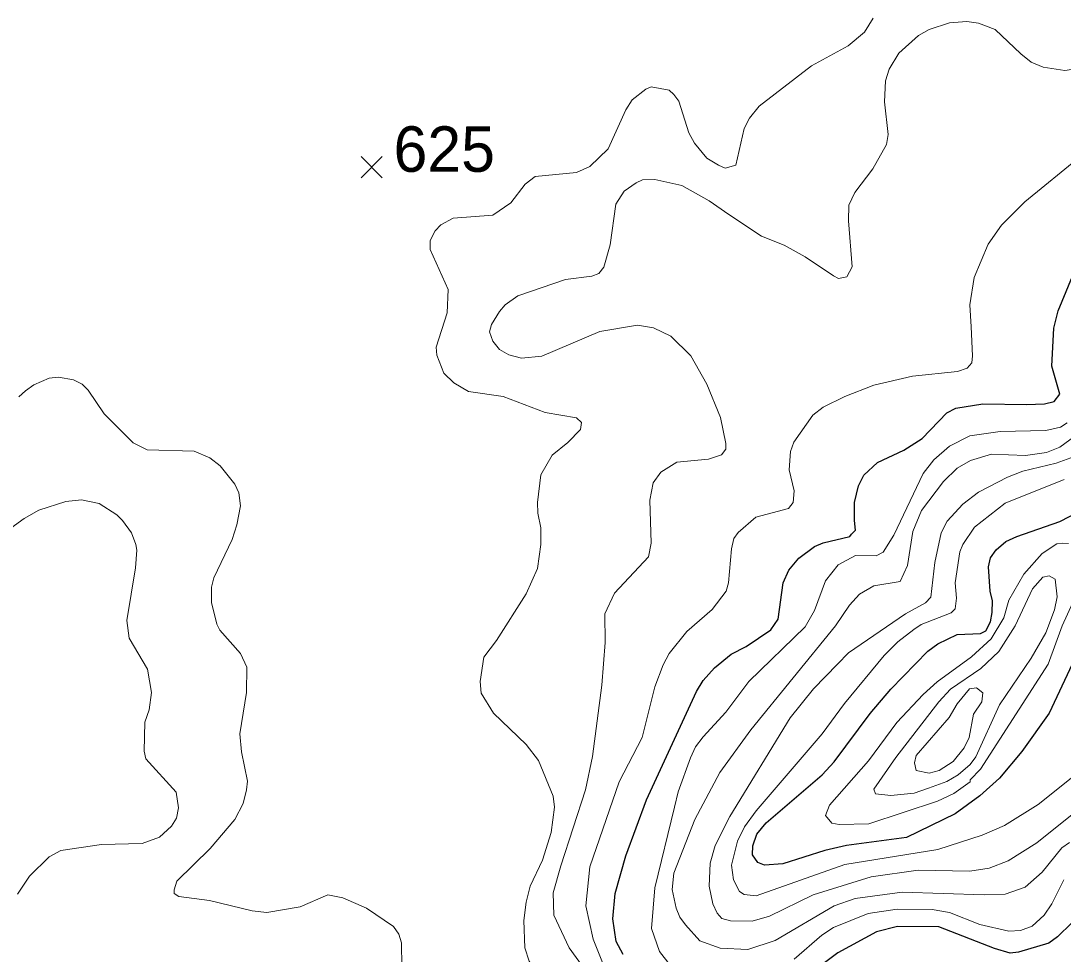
# Model space of a CAD drawing. Extents: x 294.2 to 320.3, y 7482.7 to 7510.7.
# Drawn here: x 308.568 to 310.402, y 7489.428 to 7491.07 of the extents above; entities that cross this region are included whole.
import ezdxf
from ezdxf.enums import TextEntityAlignment as Align

# ---------------------------------------------------------------- set-up
doc = ezdxf.new("R2010")
doc.units = 0
doc.header["$LTSCALE"] = 0.032
for name, color, linetype, lineweight in [('1', 7, 'Continuous', 25), ('2', 7, 'Continuous', 13), ('21', 7, 'Continuous', 25)]:
    doc.layers.add(name, color=color, linetype=linetype, lineweight=lineweight)
doc.layers.add('61', color=7, linetype='Continuous')

msp = doc.modelspace()

# ---------------------------------------------------------------- linework, layer by layer
at = {"layer": '1'}
for points in [[(309.6282, 7489.427), (309.6154, 7489.45), (309.6097, 7489.4896), (309.6141, 7489.5343), (309.6327, 7489.6007), (309.669, 7489.699), (309.7572, 7489.8896), (309.769, 7489.9093), (309.7889, 7489.9313), (309.818, 7489.9557), (309.8447, 7489.969), (309.888, 7489.9981), (309.9008, 7490.017), (309.9098, 7490.0808), (309.9193, 7490.1031), (309.9372, 7490.1242), (309.9647, 7490.1446), (309.98, 7490.1516), (310.0266, 7490.1625), (310.0298, 7490.1664), (310.0366, 7490.1739), (310.0349, 7490.1906), (310.0349, 7490.2225), (310.0419, 7490.2519), (310.0515, 7490.2704), (310.0758, 7490.2928), (310.1218, 7490.3145), (310.1543, 7490.3349), (310.1977, 7490.3802), (310.2137, 7490.3885), (310.261, 7490.3962), (310.3376, 7490.3949), (310.3695, 7490.3962), (310.3867, 7490.4), (310.3963, 7490.4128), (310.3823, 7490.462), (310.3861, 7490.529), (310.3937, 7490.5597), (310.4257, 7490.6376)], [(310.418, 7489.9378), (310.3778, 7489.8516), (310.3299, 7489.7839), (310.2903, 7489.7373), (310.2558, 7489.706), (310.2124, 7489.6747), (310.1269, 7489.6326), (310.0209, 7489.6185), (309.9829, 7489.6098), (309.9091, 7489.5867), (309.8764, 7489.584), (309.8647, 7489.5888), (309.8558, 7489.6023), (309.8564, 7489.6184), (309.8631, 7489.6388), (309.8797, 7489.6587), (309.9779, 7489.7432), (309.9995, 7489.7658), (310.0627, 7489.8508), (310.0992, 7489.8939), (310.1641, 7489.9606), (310.1819, 7489.9735), (310.2157, 7489.9902), (310.2568, 7489.9918), (310.2662, 7489.9967), (310.2745, 7490.0123), (310.2773, 7490.029), (310.2779, 7490.0494), (310.274, 7490.0661), (310.2712, 7490.1089), (310.2746, 7490.125), (310.2845, 7490.139), (310.3012, 7490.1535), (310.3206, 7490.1626), (310.3963, 7490.1887), (310.4295, 7490.2059)], [(310.4174, 7489.4826), (310.3925, 7489.4582), (310.3771, 7489.4467), (310.324, 7489.431), (310.3091, 7489.4294), (310.2816, 7489.4373), (310.1837, 7489.4757), (310.1106, 7489.4765), (310.0739, 7489.4671), (310.0055, 7489.4301), (309.898, 7489.3492)]]:
    msp.add_lwpolyline(points, dxfattribs=at)
at = {"layer": '2'}
for points in [[(309.4551, 7489.4385), (309.4533, 7489.487), (309.4571, 7489.5189), (309.4641, 7489.547), (309.4858, 7489.593), (309.5011, 7489.6415), (309.5069, 7489.6862), (309.5049, 7489.7054), (309.4788, 7489.7686), (309.4571, 7489.7967), (309.3996, 7489.8516), (309.3779, 7489.8867), (309.376, 7489.9071), (309.3824, 7489.9499), (309.4047, 7489.9792), (309.4571, 7490.0616), (309.4769, 7490.1063), (309.4832, 7490.1485), (309.4832, 7490.1778), (309.4775, 7490.2034), (309.4769, 7490.2225), (309.4832, 7490.2711), (309.5031, 7490.3055), (309.5305, 7490.3279), (309.5529, 7490.3508), (309.5547, 7490.363), (309.5459, 7490.3713), (309.4909, 7490.3808), (309.4169, 7490.4089), (309.3556, 7490.4179), (309.33, 7490.4326), (309.3121, 7490.4498), (309.3, 7490.4818), (309.2988, 7490.4958), (309.3179, 7490.5558), (309.3198, 7490.5973), (309.2885, 7490.6675), (309.2885, 7490.6835), (309.2968, 7490.7001), (309.307, 7490.711), (309.3288, 7490.7225), (309.3983, 7490.7276), (309.4303, 7490.7493), (309.4552, 7490.7825), (309.473, 7490.7958), (309.5459, 7490.8029), (309.5695, 7490.8137), (309.6014, 7490.8444), (309.6327, 7490.9134), (309.6435, 7490.9306), (309.6678, 7490.9497), (309.6774, 7490.9536), (309.7087, 7490.9478), (309.7169, 7490.9402), (309.7259, 7490.9287), (309.7437, 7490.8725), (309.7534, 7490.8546), (309.775, 7490.8284), (309.7955, 7490.8157), (309.8076, 7490.8106), (309.8261, 7490.8157), (309.8408, 7490.8802), (309.8504, 7490.8987), (309.867, 7490.9197), (309.9596, 7490.9906), (310.024, 7491.0257), (310.0528, 7491.05), (310.0681, 7491.0743)], [(309.5746, 7489.381), (309.5331, 7489.4385), (309.5056, 7489.496), (309.5049, 7489.5355), (309.5184, 7489.5828), (309.5618, 7489.7169), (309.5739, 7489.7756), (309.5905, 7489.9007), (309.5963, 7489.9761), (309.5956, 7490.0265), (309.6129, 7490.0629), (309.6723, 7490.1267), (309.6773, 7490.151), (309.6748, 7490.2264), (309.6806, 7490.257), (309.694, 7490.2755), (309.7221, 7490.2934), (309.7783, 7490.2985), (309.8012, 7490.3062), (309.8089, 7490.3164), (309.8089, 7490.326), (309.7993, 7490.3719), (309.7751, 7490.4307), (309.747, 7490.4805), (309.7118, 7490.5149), (309.6812, 7490.5296), (309.6531, 7490.5341), (309.5867, 7490.5233), (309.4846, 7490.4798), (309.4488, 7490.476), (309.4264, 7490.4824), (309.4105, 7490.4913), (309.3983, 7490.506), (309.3926, 7490.5226), (309.3964, 7490.5354), (309.4105, 7490.5584), (309.42, 7490.5699), (309.4424, 7490.5858), (309.5267, 7490.6145), (309.5727, 7490.6203), (309.5848, 7490.6254), (309.5937, 7490.6362), (309.6052, 7490.6759), (309.6148, 7490.7474), (309.6295, 7490.7704), (309.6506, 7490.785), (309.662, 7490.7901), (309.6838, 7490.7908), (309.731, 7490.7799), (309.7795, 7490.7531), (309.814, 7490.7288), (309.8715, 7490.6911), (309.9111, 7490.6752), (309.9481, 7490.6548), (309.9979, 7490.6209), (310.0068, 7490.6165), (310.0215, 7490.6196), (310.0311, 7490.6369), (310.0247, 7490.718), (310.0253, 7490.7454), (310.0356, 7490.7678), (310.0675, 7490.8093), (310.0917, 7490.8521), (310.0943, 7490.87), (310.0879, 7490.9274), (310.0898, 7490.9645), (310.0962, 7490.9849), (310.1134, 7491.013), (310.1479, 7491.0443), (310.1664, 7491.0545), (310.2022, 7491.0666), (310.2329, 7491.0685), (310.2533, 7491.066)], [(310.2533, 7491.066), (310.2827, 7491.0545), (310.328, 7491.0117), (310.3458, 7490.997), (310.3669, 7490.9881), (310.4052, 7490.9823), (310.4244, 7490.9855)], [(310.434, 7490.8322), (310.335, 7490.7512), (310.2941, 7490.7103), (310.2705, 7490.6771), (310.2456, 7490.6184), (310.2379, 7490.5699), (310.2405, 7490.5316), (310.243, 7490.4805), (310.2418, 7490.4683), (310.2335, 7490.4588), (310.2163, 7490.453), (310.1371, 7490.4447), (310.0694, 7490.4288), (310.0183, 7490.4089), (309.98, 7490.3898), (309.9615, 7490.3757), (309.9283, 7490.3285), (309.9225, 7490.3119), (309.92, 7490.28), (309.9289, 7490.243), (309.927, 7490.2225), (309.9187, 7490.2117), (309.8613, 7490.1964), (309.8306, 7490.1695), (309.8229, 7490.1587), (309.8185, 7490.1408), (309.8134, 7490.0808), (309.8095, 7490.0661), (309.7846, 7490.0342), (309.7399, 7489.9952), (309.7087, 7489.9569), (309.6984, 7489.9365), (309.6837, 7489.8982), (309.6614, 7489.8088), (309.6206, 7489.7309), (309.5695, 7489.5815), (309.5624, 7489.5126), (309.5752, 7489.4538), (309.5918, 7489.413)], [(308.5645, 7490.4083), (308.576, 7490.4185), (308.5907, 7490.4294), (308.6175, 7490.4409), (308.6341, 7490.4428), (308.6603, 7490.4383), (308.6756, 7490.4307), (308.6864, 7490.4198), (308.7145, 7490.3783), (308.7656, 7490.3272), (308.7899, 7490.3151), (308.8729, 7490.3126), (308.9003, 7490.3011), (308.9188, 7490.287), (308.9444, 7490.2545), (308.9514, 7490.2391), (308.9546, 7490.2162), (308.9482, 7490.183), (308.9399, 7490.1574), (308.9073, 7490.0897), (308.9035, 7490.0731), (308.9035, 7490.0463), (308.9125, 7490.008), (308.9182, 7489.9978), (308.9546, 7489.9569), (308.9655, 7489.9327), (308.9648, 7489.888), (308.9533, 7489.8152), (308.9559, 7489.7833), (308.9668, 7489.7322), (308.9648, 7489.7169), (308.9591, 7489.6926), (308.9444, 7489.6645), (308.901, 7489.6134), (308.8422, 7489.5559), (308.8378, 7489.5406), (308.8378, 7489.5342), (308.8461, 7489.5291), (308.8997, 7489.5221), (308.9751, 7489.5036), (309.0006, 7489.501), (309.0593, 7489.5106), (309.1079, 7489.5317), (309.1347, 7489.5266), (309.1761, 7489.5087), (309.2234, 7489.4761), (309.233, 7489.4628), (309.2375, 7489.4474), (309.2381, 7489.4053)], [(309.7106, 7489.4085), (309.6921, 7489.4321), (309.678, 7489.473), (309.6837, 7489.5445), (309.7182, 7489.6862), (309.7246, 7489.713), (309.7463, 7489.7731), (309.7555, 7489.7924), (309.7687, 7489.8102), (309.8084, 7489.8536), (309.8492, 7489.9073), (309.9481, 7490.0035), (309.9647, 7490.0323), (309.9838, 7490.0846), (310.0062, 7490.1127), (310.0368, 7490.1293), (310.0732, 7490.1287), (310.0853, 7490.1351), (310.1045, 7490.165), (310.1562, 7490.2736), (310.1747, 7490.2972), (310.2022, 7490.3215), (310.238, 7490.3394), (310.2916, 7490.347), (310.372, 7490.3489), (310.3976, 7490.3547), (310.4097, 7490.3624)], [(310.4135, 7489.6243), (310.4001, 7489.6147), (310.3656, 7489.5719), (310.3356, 7489.5457), (310.3005, 7489.5329), (310.2635, 7489.5317), (310.1192, 7489.5368), (310.0362, 7489.5253), (309.9992, 7489.5125), (309.8957, 7489.4519), (309.8472, 7489.4359), (309.7987, 7489.4384), (309.7629, 7489.4512), (309.7374, 7489.4794), (309.7278, 7489.4928), (309.7214, 7489.5087), (309.7144, 7489.5413), (309.7169, 7489.57), (309.754, 7489.6645), (309.798, 7489.7475), (309.8529, 7489.8222), (310.0017, 7490.0055), (310.026, 7490.0418), (310.0439, 7490.061), (310.0694, 7490.0756), (310.1154, 7490.0833), (310.1281, 7490.1114), (310.1377, 7490.1715), (310.153, 7490.2085), (310.192, 7490.2595), (310.2156, 7490.2825), (310.2392, 7490.296), (310.2763, 7490.3075), (310.3363, 7490.3049), (310.3733, 7490.31), (310.3963, 7490.3196), (310.4231, 7490.3393)], [(310.4221, 7490.3035), (310.3899, 7490.2915), (310.3312, 7490.2774), (310.3043, 7490.2666), (310.2533, 7490.2404), (310.2258, 7490.2193), (310.1983, 7490.1893), (310.1875, 7490.1689), (310.1766, 7490.1166), (310.1696, 7490.0559), (310.16, 7490.0457), (310.1249, 7490.0265), (310.0247, 7489.9576), (310.0049, 7489.9378), (309.9628, 7489.8944), (309.9219, 7489.8433), (309.8159, 7489.6696), (309.7897, 7489.6185), (309.7808, 7489.5879), (309.7795, 7489.547), (309.7859, 7489.5164), (309.7936, 7489.4998), (309.8018, 7489.4902), (309.8166, 7489.4864), (309.8549, 7489.4857), (309.8855, 7489.4946), (309.9621, 7489.5317), (310.0643, 7489.5636), (310.1473, 7489.5751), (310.238, 7489.5738), (310.2724, 7489.5789), (310.3056, 7489.5917), (310.356, 7489.6236), (310.418, 7489.6734)], [(310.425, 7489.7443), (310.3586, 7489.6907), (310.2993, 7489.6537), (310.2597, 7489.6371), (310.1818, 7489.6115), (310.0183, 7489.5853), (309.8619, 7489.5304), (309.8408, 7489.5323), (309.8325, 7489.538), (309.8223, 7489.5585), (309.8185, 7489.5841), (309.8293, 7489.6262), (309.8415, 7489.6517), (309.8619, 7489.6798), (309.9781, 7489.8152), (310.0177, 7489.8688), (310.0873, 7489.9531), (310.1115, 7489.9773), (310.1396, 7489.999), (310.1524, 7490.0074), (310.2054, 7490.0284), (310.2124, 7490.0354), (310.2149, 7490.054), (310.2124, 7490.0808), (310.2207, 7490.1357), (310.2258, 7490.1485), (310.2462, 7490.1791), (310.3005, 7490.2212), (310.404, 7490.263)], [(308.5198, 7490.1555), (308.5734, 7490.1944), (308.5996, 7490.2091), (308.6468, 7490.2238), (308.6743, 7490.227), (308.7056, 7490.2206), (308.7369, 7490.2008), (308.7465, 7490.1906), (308.7624, 7490.1689), (308.7701, 7490.1485), (308.772, 7490.1383), (308.7694, 7490.1076), (308.7541, 7490.0144), (308.7586, 7489.9838), (308.7905, 7489.9288), (308.7975, 7489.888), (308.7937, 7489.8573), (308.786, 7489.8356), (308.7847, 7489.7845), (308.7879, 7489.7711), (308.841, 7489.7124), (308.8454, 7489.6849), (308.8416, 7489.6671), (308.8327, 7489.653), (308.8116, 7489.6332), (308.781, 7489.6223), (308.7095, 7489.6204), (308.6379, 7489.6102), (308.6175, 7489.5987), (308.583, 7489.5649), (308.562, 7489.533)], [(310.4116, 7490.1504), (310.4014, 7490.151), (310.3912, 7490.1497), (310.3656, 7490.1325), (310.3331, 7490.0961), (310.3069, 7490.0502), (310.2979, 7490.0195), (310.2756, 7489.9825), (310.2411, 7489.9505), (310.1805, 7489.9065), (310.1559, 7489.8847), (310.1096, 7489.835), (310.0598, 7489.7679), (309.9909, 7489.69), (309.9838, 7489.6715), (309.9953, 7489.6581), (310.0081, 7489.6555), (310.0605, 7489.6568), (310.1811, 7489.697), (310.21, 7489.7102), (310.2386, 7489.7309), (310.2386, 7489.7341), (310.2571, 7489.7532), (310.3758, 7489.9378), (310.4008, 7490.0055), (310.4352, 7490.0808)], [(310.4033, 7489.5585), (310.3822, 7489.5164), (310.3688, 7489.496), (310.3478, 7489.4768), (310.3274, 7489.4691), (310.3069, 7489.4678), (310.2558, 7489.48), (310.2022, 7489.501), (310.1716, 7489.5061), (310.1103, 7489.5068), (310.0592, 7489.4991), (309.9979, 7489.4742), (309.9775, 7489.4608), (309.9289, 7489.4187)], [(309.6441, 7489.1499), (309.6429, 7489.1665), (309.6346, 7489.1933), (309.6148, 7489.2284), (309.473, 7489.3995), (309.4622, 7489.4155), (309.4551, 7489.4385)]]:
    msp.add_lwpolyline(points, dxfattribs=at)
for points in [[(310.1836, 7489.8713), (310.2039, 7489.8938), (310.2577, 7489.9301), (310.289, 7489.9601), (310.3178, 7490.0055), (310.3484, 7490.0706), (310.3663, 7490.091), (310.3778, 7490.0935), (310.388, 7490.0872), (310.3918, 7490.0565), (310.3873, 7490.0336), (310.372, 7489.9927), (310.3459, 7489.9486), (310.2903, 7489.8663), (310.2488, 7489.7749), (310.2386, 7489.7615), (310.2175, 7489.743), (310.1977, 7489.7315), (310.1652, 7489.7194), (310.1402, 7489.7111), (310.0988, 7489.7066), (310.0719, 7489.7098), (310.0694, 7489.7181), (310.1077, 7489.7737)], [(310.2015, 7489.8442), (310.1434, 7489.7769), (310.1409, 7489.7641), (310.1434, 7489.7507), (310.1665, 7489.7462), (310.1843, 7489.7507), (310.2086, 7489.7666), (310.2284, 7489.7909), (310.2367, 7489.8088), (310.2443, 7489.8497), (310.259, 7489.8714), (310.2609, 7489.8873), (310.2501, 7489.8963), (310.2373, 7489.8943), (310.2156, 7489.8682)]]:
    msp.add_lwpolyline(points, close=True, dxfattribs=at)
at = {"layer": '21'}
for p, q in [((309.1665, 7490.8309), (309.204, 7490.7934)), ((309.204, 7490.8309), (309.1665, 7490.7934))]:
    msp.add_line(p, q, dxfattribs=at)

# ---------------------------------------------------------------- texts
at = {"layer": '61'}
msp.add_text('625', height=0.08, dxfattribs=at).set_placement((309.313, 7490.8042), align=Align.CENTER)

doc.saveas('drawing.dxf')
